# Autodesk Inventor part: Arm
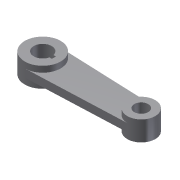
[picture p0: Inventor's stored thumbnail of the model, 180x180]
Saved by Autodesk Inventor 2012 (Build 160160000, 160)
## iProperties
Created: 2009-04
Part Number: Arm
Material: Default
Document SubType Name: Modeling
Designer: Sham
Density: 1 g/cm^3
Sheet Metal Width: 0.000 mm
Sheet Metal Length: 0.000 mm
Sheet Metal Area: 0.000 mm^2
Author: Sham
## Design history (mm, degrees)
sketch "Sketch1"
  geometry: L1 (27.436, 6.3)-(35.136, 6.3); L2 (35.136, 6.3)-(35.136, -6.3); L3 (35.136, -6.3)-(27.436, -6.3); C1 r 56.25 at (0, 0); C2 r 43.75 at (309, 0); C3 r 21.9 at (309, 0); A1 r 28.15 centre (0, 0) between (27.436, 6.3) and (27.436, -6.3); 1 further point
  constraints: 6 end point, 4 centre point, 3 coincident, 2 point on circle, 1 horizontal, 1 parallel, 1 perpendicular, 1 other
  dimensions: "d0" = 112.5 diameter of C1; "d2" = 87.5 diameter of C2; "d3" = 56.3 diameter of A1; "d4" = 43.8 diameter of C3; "d7" = 12.6 distance of L1.end L2.end; "d8" = 7.7 distance of L1.start L1.end; "d9" = 7.7 distance of L2.end L3.end
extrude "Extrusion1" join sketch "Sketch1" stored distance "d5" = 62.5; taper "d6" = 0 deg
sketch "Sketch2"
  geometry: L1 (2.275, 56.204)-(310.77, 43.714); L2 (2.275, -56.204)-(310.77, -43.714); A1 r 56.25 centre (0, 0) between (2.275, 56.204) and (2.275, -56.204) reference; A2 r 43.75 centre (309, 0) between (310.77, 43.714) and (310.77, -43.714) reference
  constraints: 4 end point, 4 point on circle, 4 tangent
extrude "Extrusion2" join sketch "Sketch2" stored distance "d10" = 25; taper "d11" = 0 deg
body "Solid1"
other parameters: "Thickness" = 0.5, "BendRadius" = 0.5 (= Thickness), "BendReliefWidth" = 0.5 (= Thickness), "BendReliefDepth" = 0.25 (= 0.5 x Thickness), "CornerReliefSize" = 2 (= 4 x Thickness), "SeamGap" = 0.01, "MinimumRemnant" = 1 (= 2 x Thickness), "TransitionRadius" = 0.5 (= BendRadius), "JacobiRadiusSize" = 0.5 (= BendRadius), "GapSize" = 0.5 (= Thickness)
